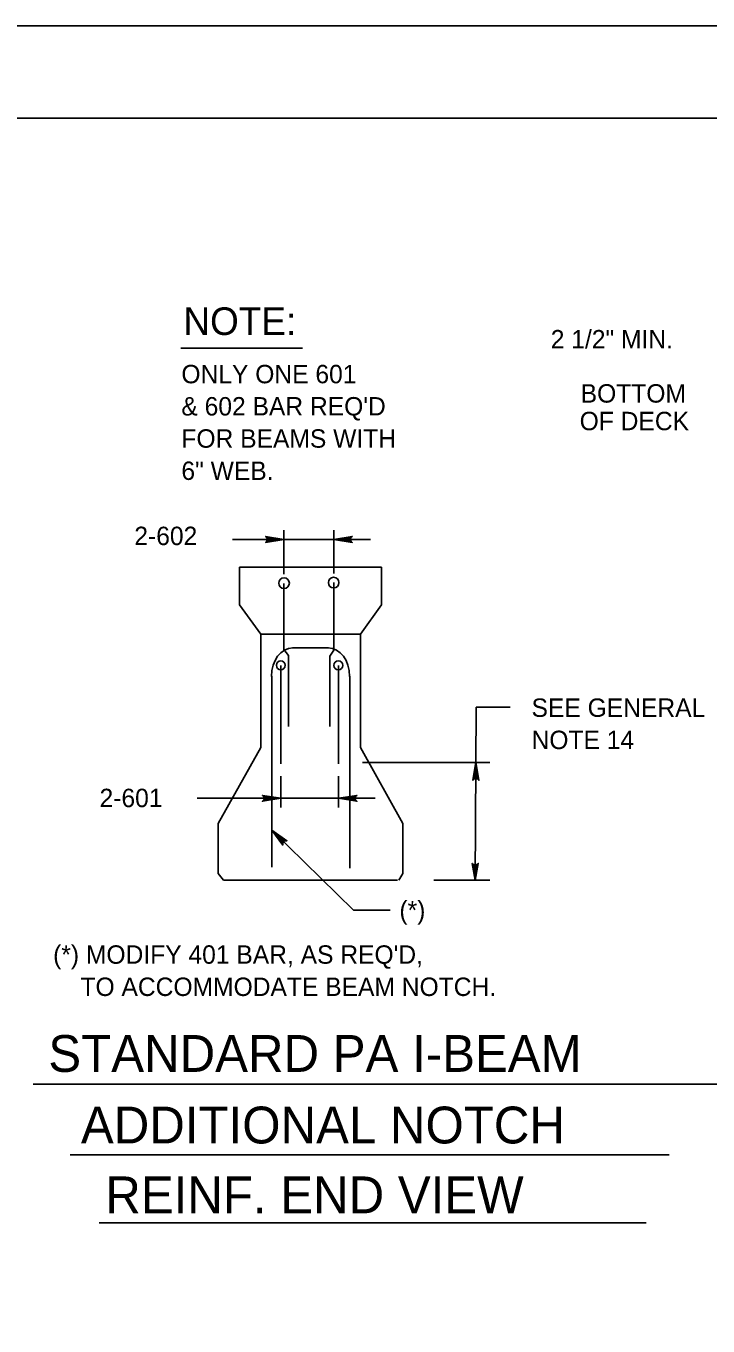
# Model space of a CAD drawing. Extents: x 637933 to 640019, y 298854 to 300042.
# Drawn here: x 638388.8 to 638500, y 299830.3 to 300042.1 of the extents above; entities that cross this region are included whole.
import ezdxf

# ---------------------------------------------------------------- set-up
doc = ezdxf.new("R2010")
doc.units = 0
doc.layers.add('1', color=7, linetype='Continuous')
doc.layers.add('PLT-BNDY', color=7, linetype='Continuous')

msp = doc.modelspace()

# ---------------------------------------------------------------- linework, layer by layer
at = {"layer": '1'}
for p, q in [((638023.93, 300027.12), (638809.94, 300027.12)), ((638414.06, 299989.62), (638433.89, 299989.62)), ((638430.89, 299952.79), (638430.89, 299959.96)), ((638439.02, 299952.91), (638439.02, 299959.96)), ((638422.48, 299958.46), (638445.02, 299958.46)), ((638446.77, 299953.91), (638423.64, 299953.91)), ((638423.64, 299947.79), (638423.64, 299953.91)), ((638446.77, 299947.79), (638446.77, 299953.91)), ((638430.89, 299940.54), (638430.89, 299951.29)), ((638439.02, 299940.41), (638439.02, 299951.41)), ((638427.14, 299943.04), (638423.64, 299947.79)), ((638443.39, 299943.04), (638446.77, 299947.79)), ((638443.39, 299943.04), (638427.14, 299943.04)), ((638443.39, 299943.04), (638427.14, 299943.04)), ((638427.14, 299924.54), (638427.14, 299943.04)), ((638443.39, 299924.54), (638443.39, 299943.04)), ((638430.89, 299940.54), (638431.64, 299939.54)), ((638438.14, 299940.79), (638432.27, 299940.79)), ((638439.02, 299940.41), (638438.39, 299939.41)), ((638430.39, 299921.89), (638430.39, 299937.91)), ((638431.64, 299927.97), (638431.64, 299939.54)), ((638438.39, 299927.97), (638438.39, 299939.41)), ((638439.77, 299921.89), (638439.77, 299937.91)), ((638428.89, 299905.04), (638428.89, 299936.16)), ((638441.64, 299904.91), (638441.64, 299936.16)), ((638462.07, 299902.91), (638462.23, 299931.14)), ((638462.23, 299931.14), (638467.74, 299931.14)), ((638420.14, 299912.16), (638427.14, 299924.54)), ((638443.39, 299924.54), (638450.27, 299912.16)), ((638464.43, 299922.09), (638443.67, 299922.09)), ((638430.39, 299919.89), (638430.39, 299914.77)), ((638439.77, 299919.89), (638439.77, 299914.77)), ((638416.73, 299916.27), (638445.77, 299916.27)), ((638420.14, 299904.04), (638420.14, 299912.16)), ((638428.89, 299911.1), (638442.21, 299898.06)), ((638450.27, 299904.04), (638450.27, 299912.16)), ((638420.14, 299904.04), (638421.02, 299902.91)), ((638450.27, 299904.04), (638449.64, 299902.91)), ((638449.39, 299902.91), (638421.02, 299902.91)), ((638464.43, 299902.91), (638455.3, 299902.91)), ((638448.21, 299898.06), (638442.21, 299898.06)), ((638501.63, 299869.7), (638390.01, 299869.7)), ((638493.7, 299858.15), (638396.03, 299858.15)), ((638489.96, 299847.1), (638400.75, 299847.1))]:
    msp.add_line(p, q, dxfattribs=at)
for points in [[(638428.04, 299958.82), (638428.14, 299958.61), (638430.89, 299958.46), (638428.04, 299958.82), (638427.89, 299958.94), (638430.89, 299958.46), (638428.15, 299958.32), (638428.05, 299958.12), (638430.89, 299958.46), (638427.89, 299957.98), (638428.05, 299958.12)], [(638441.87, 299958.1), (638441.76, 299958.31), (638439.02, 299958.46), (638441.87, 299958.1), (638442.02, 299957.97), (638439.02, 299958.46), (638441.76, 299958.59), (638441.86, 299958.8), (638439.02, 299958.46), (638442.02, 299958.94), (638441.86, 299958.8)], [(638461.81, 299919.46), (638462.06, 299919.46), (638462.18, 299922.09), (638461.81, 299919.46), (638461.68, 299919.21), (638462.18, 299922.09), (638462.31, 299919.46), (638462.56, 299919.46), (638462.18, 299922.09), (638462.68, 299919.21), (638462.56, 299919.46)], [(638427.54, 299916.63), (638427.64, 299916.42), (638430.39, 299916.27), (638427.54, 299916.63), (638427.39, 299916.75), (638430.39, 299916.27), (638427.65, 299916.13), (638427.55, 299915.93), (638430.39, 299916.27), (638427.39, 299915.79), (638427.55, 299915.93)], [(638442.62, 299915.91), (638442.51, 299916.12), (638439.77, 299916.27), (638442.62, 299915.91), (638442.77, 299915.79), (638439.77, 299916.27), (638442.51, 299916.41), (638442.61, 299916.61), (638439.77, 299916.27), (638442.77, 299916.75), (638442.61, 299916.61)], [(638430.68, 299908.85), (638430.75, 299909.07), (638428.89, 299911.1), (638430.68, 299908.85), (638430.7, 299908.66), (638428.89, 299911.1), (638430.95, 299909.28), (638431.16, 299909.36), (638428.89, 299911.1), (638431.37, 299909.35), (638431.16, 299909.36)], [(638462.44, 299905.54), (638462.19, 299905.41), (638462.07, 299902.91), (638462.44, 299905.54), (638462.57, 299905.66), (638462.07, 299902.91), (638461.94, 299905.41), (638461.69, 299905.54), (638462.07, 299902.91), (638461.57, 299905.66), (638461.69, 299905.54)]]:
    msp.add_lwpolyline(points, dxfattribs=at)
for centre, radius in [((638430.9, 299951.32), 0.866), ((638438.99, 299951.42), 0.866), ((638430.37, 299937.94), 0.722), ((638439.75, 299937.93), 0.722)]:
    msp.add_circle(centre, radius, dxfattribs=at)
for centre, major_axis, start_param, end_param in [((638432.32, 299936.14), (0, -4.64), 3.141593, 4.712389), ((638438.12, 299936.14), (0, 4.64), 4.712389, 6.283185)]:
    msp.add_ellipse(centre, major_axis=major_axis, ratio=0.75, start_param=start_param, end_param=end_param, dxfattribs=at)
at = {"layer": 'PLT-BNDY'}
msp.add_lwpolyline([(637983.93, 300042.12), (638824.93, 300042.12), (638824.93, 299448.12), (637983.93, 299448.12)], close=True, dxfattribs=at)

# ---------------------------------------------------------------- texts
at = {"layer": '1'}
for s, height, p in [('NOTE:', 4.5, (638414.5, 299991.77)), ('2 1/2" MIN.', 3, (638474.38, 299989.58)), ('ONLY ONE 601', 3, (638414.17, 299983.9)), ('BOTTOM', 3, (638479.26, 299980.75)), ("& 602 BAR REQ'D", 3, (638414.17, 299978.65)), ('OF DECK', 3, (638479.09, 299976.25)), ('FOR BEAMS WITH', 3, (638414.17, 299973.4)), ('6" WEB.', 3, (638414.17, 299968.15)), ('2-602', 3, (638406.5, 299957.53)), ('SEE GENERAL', 3, (638471.25, 299929.54)), ('NOTE 14', 3, (638471.25, 299924.29)), ('2-601', 3, (638400.83, 299914.83)), ('(*)', 3, (638449.71, 299896.56)), ("(*) MODIFY 401 BAR, AS REQ'D,", 3, (638393.26, 299889.31)), ('    TO ACCOMMODATE BEAM NOTCH.', 3, (638393.26, 299884.06)), ('STANDARD PA I-BEAM', 6, (638392.48, 299871.69)), ('ADDITIONAL NOTCH', 6, (638397.79, 299860.03)), ('REINF. END VIEW', 6, (638401.76, 299848.65))]:
    msp.add_text(s, height=height, dxfattribs=at).set_placement(p)

doc.saveas('drawing.dxf')
